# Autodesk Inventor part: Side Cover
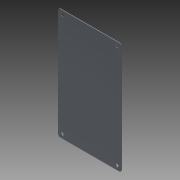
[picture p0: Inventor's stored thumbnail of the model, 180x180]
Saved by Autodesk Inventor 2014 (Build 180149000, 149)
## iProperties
Created: 2007-07
Part Number: Side Cover
Material: Generic
Document SubType Name: Modeling
Designer: PaulN
Density: 1 g/cm^3
Appearance: Zinc
Author: PaulN
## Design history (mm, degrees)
sketch "Sketch1"
  geometry: L1 (-94, -176.5)-(94, -176.5) reference; L2 (-100, -170.5)-(-100, 170.5) reference; L3 (94, 176.5)-(-94, 176.5) reference; L4 (100, -170.5)-(100, 170.5) reference; C1 r 4.5 at (-87, -163.5) reference; C2 r 4.5 at (-87, 163.5) reference; C3 r 4.5 at (87, 163.5) reference; C4 r 4.5 at (87, -163.5) reference; A1 r 6 centre (-94, -170.5) between (-100, -170.5) and (-94, -176.5) reference; A2 r 6 centre (-94, 170.5) between (-94, 176.5) and (-100, 170.5) reference; A3 r 6 centre (94, 170.5) between (100, 170.5) and (94, 176.5) reference; A4 r 6 centre (94, -170.5) between (94, -176.5) and (100, -170.5) reference; 1 further point
extrude "Extrusion1" new body sketch "Sketch1" distance "d0" = 2; taper "d1" = 0 deg
body "Solid1"
node "Reference1"
node "Reference2"
node "Reference3"
node "Reference4"
node "Reference5"
node "Reference6"
node "Reference7"
node "Reference8"
node "Reference9"
node "Reference10"
node "Reference11"
node "Reference12"
